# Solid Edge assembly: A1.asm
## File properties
Author: edge
Template: Jis Assembly.asm
Last saved by: edge
Revision: 15
Application: Solid Edge
Username: edge
文書内容のタイプ: 1
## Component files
B1.asm
B2.asm
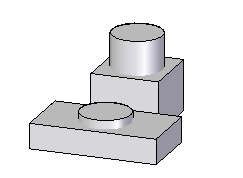
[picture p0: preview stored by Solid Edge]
